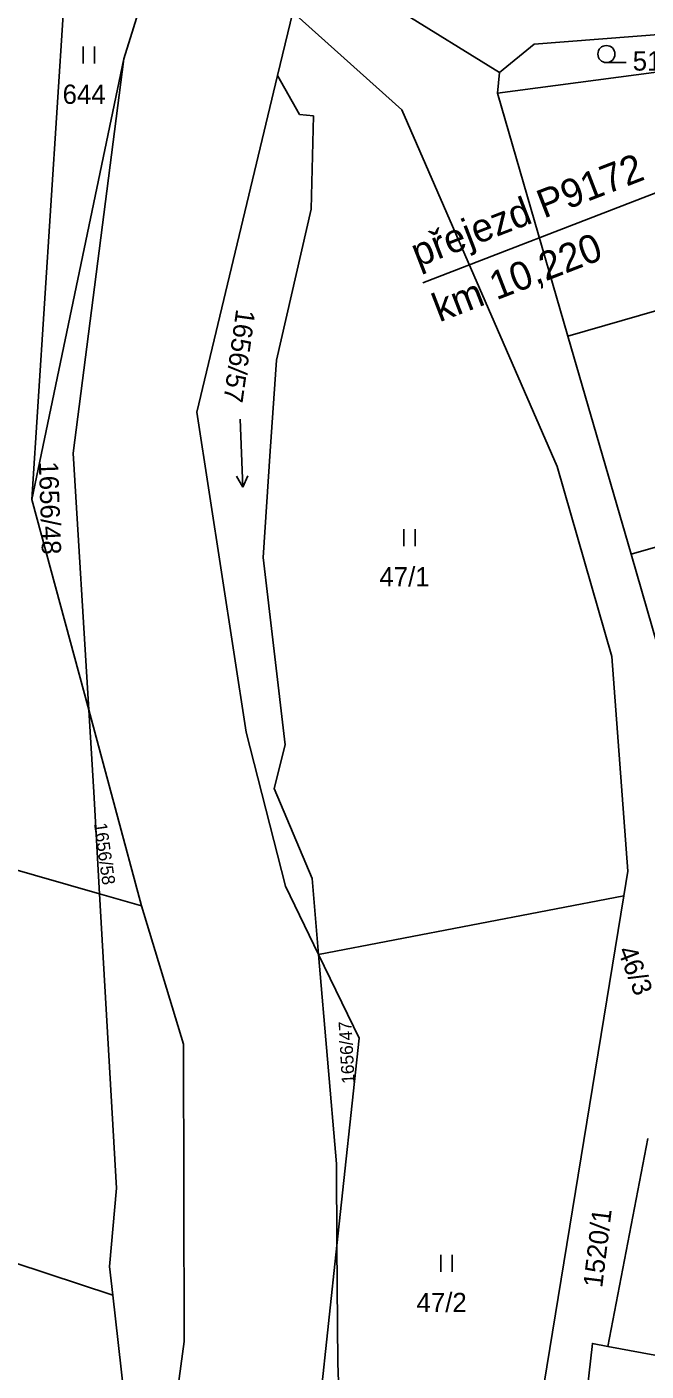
# Model space of a CAD drawing. Extents: x -553916 to -552953, y -1067469 to -1066637.
# Drawn here: x -553633.4 to -553578.9, y -1067025.6 to -1066907.3 of the extents above; entities that cross this region are included whole.
import ezdxf

# ---------------------------------------------------------------- set-up
doc = ezdxf.new("R2010")
doc.units = 0
for name, color, linetype in [('Hranice parcel', 7, 'Continuous'), ('Parcelní čísla', 7, 'Continuous'), ('Přejezd - štěrkové lože', 7, 'Continuous'), ('Značky kultur', 7, 'Continuous')]:
    doc.layers.add(name, color=color, linetype=linetype)

msp = doc.modelspace()

# ---------------------------------------------------------------- linework, layer by layer
at = {"layer": 'Hranice parcel'}
for p, q in [((-553624.88, -1066910.1), (-553621.57, -1066899.49)), ((-553630.21, -1066905.76), (-553632.98, -1066948.88)), ((-553610.01, -1066906), (-553611.35, -1066911.57)), ((-553591.81, -1066911.32), (-553600.63, -1066905.86)), ((-553591.97, -1066913.14), (-553561.91, -1066909.12)), ((-553632.98, -1066948.88), (-553624.88, -1066910.1)), ((-553611.35, -1066911.57), (-553609.41, -1066915.01)), ((-553591.97, -1066913.14), (-553591.81, -1066911.32)), ((-553585.78, -1066934.51), (-553591.97, -1066913.14)), ((-553585.78, -1066934.51), (-553556.97, -1066926.17)), ((-553580.22, -1066953.72), (-553585.78, -1066934.51)), ((-553580.22, -1066953.72), (-553551.41, -1066945.38)), ((-553632.98, -1066948.88), (-553627.98, -1066967.41)), ((-553576.96, -1066964.99), (-553580.22, -1066953.72)), ((-553627.98, -1066967.41), (-553623.32, -1066984.67)), ((-553608.31, -1066982.27), (-553607.74, -1066988.95)), ((-553627.02, -1066983.6), (-553623.32, -1066984.67)), ((-553625.53, -1067009.52), (-553627.02, -1066983.6)), ((-553607.74, -1066988.95), (-553580.85, -1066983.77)), ((-553589.31, -1067035.5), (-553580.85, -1066983.77)), ((-553578.74, -1067005.13), (-553582.25, -1067023.44)), ((-553626.16, -1067016.42), (-553625.53, -1067009.52)), ((-553608.97, -1067041.18), (-553606.12, -1067014.56)), ((-553606.12, -1067014.56), (-553606.05, -1067024.93)), ((-553625.87, -1067018.94), (-553626.16, -1067016.42)), ((-553582.25, -1067023.44), (-553574.24, -1067024.96))]:
    msp.add_line(p, q, dxfattribs=at)
for points in [[(-553580.85, -1066983.77), (-553580.5, -1066981.61), (-553581.9, -1066962.72), (-553586.71, -1066945.98), (-553600.4, -1066914.59), (-553610.01, -1066906)], [(-553562.08, -1066908.37), (-553567.96, -1066907.21), (-553588.75, -1066908.8), (-553591.81, -1066911.32)], [(-553624.88, -1066910.1), (-553629.34, -1066944.82), (-553627.98, -1066967.41)], [(-553607.74, -1066988.95), (-553610.66, -1066982.93), (-553614.12, -1066969.38), (-553618.45, -1066941.2), (-553611.35, -1066911.57)], [(-553609.41, -1066915.01), (-553608.19, -1066915.13), (-553608.39, -1066923.35), (-553611.45, -1066936.62), (-553612.01, -1066944.65), (-553612.63, -1066953.99), (-553610.68, -1066970.5), (-553611.66, -1066974.34), (-553608.31, -1066982.27)], [(-553627.98, -1066967.41), (-553627.54, -1066974.67), (-553627.02, -1066983.6)], [(-553627.02, -1066983.6), (-553635.52, -1066981.16), (-553652.47, -1067024.37)], [(-553623.32, -1066984.67), (-553619.63, -1066996.83), (-553619.56, -1067023.02), (-553621.7, -1067038.64), (-553627.75, -1067062.69), (-553642.34, -1067082.27), (-553644.52, -1067088.87), (-553655.73, -1067178.24), (-553657.73, -1067185.13), (-553660.17, -1067189.87)], [(-553606.12, -1067014.56), (-553606.17, -1067007.38), (-553607.74, -1066988.95)], [(-553607.74, -1066988.95), (-553604.17, -1066996.31), (-553606.12, -1067014.56)], [(-553648.45, -1067052.9), (-553643.22, -1067013.2), (-553625.87, -1067018.94)], [(-553635.52, -1067058.6), (-553624.9, -1067027.54), (-553625.87, -1067018.94)], [(-553582.25, -1067023.44), (-553583.62, -1067023.18), (-553585.14, -1067036.63)], [(-553606.05, -1067024.93), (-553605.71, -1067033.75), (-553606.25, -1067040.6)]]:
    msp.add_lwpolyline(points, dxfattribs=at)
at = {"layer": 'Přejezd - štěrkové lože'}
msp.add_lwpolyline([(-553598.54, -1066929.82), (-553559.03, -1066914.56), (-553554.95, -1066907.55), (-553544.41, -1066903.46)], dxfattribs=at)
at = {"layer": 'Značky kultur'}
for p, q in [((-553628.46, -1066910.52), (-553628.46, -1066909.02)), ((-553627.46, -1066910.52), (-553627.46, -1066909.02)), ((-553582.39, -1066910.43), (-553580.64, -1066910.43)), ((-553614.63, -1066941.81), (-553614.42, -1066947.81)), ((-553614.42, -1066947.81), (-553614.96, -1066946.85)), ((-553614.42, -1066947.81), (-553613.96, -1066946.81)), ((-553600.24, -1066953), (-553600.24, -1066951.5)), ((-553599.24, -1066953), (-553599.24, -1066951.5)), ((-553596.97, -1067016.88), (-553596.97, -1067015.38)), ((-553595.97, -1067016.88), (-553595.97, -1067015.38))]:
    msp.add_line(p, q, dxfattribs=at)
msp.add_circle((-553582.39, -1066909.68), 0.75, dxfattribs=at)

# ---------------------------------------------------------------- texts
at = {"layer": 'Parcelní čísla'}
for s, p in [('51/7', (-553580.07, -1066911.14)), ('644', (-553630.28, -1066914.07)), ('47/1', (-553602.38, -1066956.55)), ('47/2', (-553599.11, -1067020.43))]:
    msp.add_text(s, height=1.7, dxfattribs=at).set_placement(p)
for s, height, rotation, p in [('1656/57', 1.7, 262, (-553614.98, -1066932.08)), ('1656/48', 1.7, 272, (-553632.38, -1066945.56)), ('1656/58', 1.14, 278, (-553627.52, -1066977.43)), ('46/3', 1.7, 291, (-553581.43, -1066988.58)), ('1656/47', 1.14, 93, (-553604.55, -1067000.3)), ('1520/1', 1.7, 83, (-553582.76, -1067018.33))]:
    msp.add_text(s, height=height, rotation=rotation, dxfattribs=at).set_placement(p)
at = {"layer": 'Přejezd - štěrkové lože'}
for s, p in [('přejezd P9172', (-553598.99, -1066928.46)), ('km 10,220', (-553597.1, -1066933.31))]:
    msp.add_text(s, height=2.5, rotation=21.1258, dxfattribs=at).set_placement(p)

doc.saveas('drawing.dxf')
